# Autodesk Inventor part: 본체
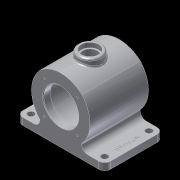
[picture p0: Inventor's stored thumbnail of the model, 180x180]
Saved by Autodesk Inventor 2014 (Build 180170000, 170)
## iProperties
Company: 한국ATC센터
Created: 2014-08
Part Number: 본체
Document SubType Name: Modeling
Designer: KYOUNG IL JANG
Density: 2.71 g/cm^3
Material: 알루미늄-6061
Mass: 1595.13 g
Surface Area: 933.382 cm^2
Volume: 588.61 cm^3
Appearance: 알루미늄 - 평지
Author: KYOUNG IL JANG
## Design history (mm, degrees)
sketch "스케치1"
  geometry: L1 (-50, 0)-(50, 0); L2 (-36.062, 36.062)-(36.062, 36.062); L3 (36.062, 36.062)-(36.062, -36.062); L4 (36.062, -36.062)-(-36.062, -36.062); L5 (-36.062, -36.062)-(-36.062, 36.062); A1 r 53.623 centre (-3.623, 0) between (36.062, -36.062) and (36.062, 36.062); A2 r 53.623 centre (3.623, 0) between (-36.062, 36.062) and (-36.062, -36.062); A3 r 53.623 centre (0, -3.623) between (36.062, 36.062) and (-36.062, 36.062); A4 r 53.623 centre (0, 3.623) between (-36.062, -36.062) and (36.062, -36.062); 4 further points
  constraints: 11 point on circle, 10 end point, 5 coincident, 4 centre point, 4 horizontal alignment, 3 equal radius, 2 horizontal, 2 parallel, 2 perpendicular, 1 midpoint
  dimensions: "d83" = 51 distance of L2.end point (0, 0); "d84" = 100 distance of L1.end L1.start
extrude "돌출1" new body sketch "스케치1" stored distance "d9" = 100; taper "d10" = 0 deg
node "작업 평면1"
sketch "스케치2"
  geometry: L1 (75, 50)-(-75, 50); L2 (-75, 50)-(-75, -50); L3 (-75, -50)-(75, -50); L4 (75, -50)-(75, 50); 4 further points
  constraints: 8 end point, 3 midpoint, 2 parallel, 2 vertical alignment, 1 horizontal, 1 horizontal alignment, 1 perpendicular
  dimensions: "d14" = 150 distance of L2.end L3.end; "d82" = 100 distance of L1.end L2.end
extrude "돌출2" join sketch "스케치2" distance "d15" = 12; taper "d16" = 0 deg
node "작업 평면3"
  node "작업 평면4"
sketch "스케치3"
  geometry: C1 r 20 at (0, 0); 1 further point
  constraints: 2 coincident, 1 centre point
  dimensions: "d19" = 40 diameter of C1
extrude "돌출3" join sketch "스케치3" stored distance "d23" = 12; taper "d24" = 0 deg
node "작업 평면6"
  node "작업 평면5"
sketch "스케치4"
  geometry: C1 r 37.5 at (0, 0); 1 further point
  constraints: 1 centre point, 1 coincident
  dimensions: "d25" = 75 diameter of C1
extrude "돌출4" cut sketch "스케치4" stored distance "d26" = 76; taper "d27" = 0 deg
sketch "스케치5"
  geometry: C1 r 30 at (0, 0); 1 further point
  constraints: 1 centre point, 1 coincident
  dimensions: "d28" = 60 diameter of C1
extrude "돌출5" cut sketch "스케치5" stored distance "d29" = 116; taper "d30" = 0 deg
hole "구멍1" diameter "d33" = 25; stored, may be unused: countersink angle "d37" = 90 deg, drill point angle "d39" = 0 deg; dims "d31" = 10, "d32" = 10, "d34" = 6, "d35" = 30, "d36" = 8, "d38" = 40
sketch "스케치6"
  geometry: L1 (-75, -50)-(-75, 50) reference; L2 (-75, 50)-(75, 50) reference; L3 (75, -50)-(-75, -50) reference; L4 (75, 50)-(75, -50) reference; L5 (0, -50)-(0, 50); L6 (-75, 0)-(75, 0); L7 (-63, -38)-(63, 38); C1 r 5.5 at (-63, -38); C2 r 5.5 at (-63, 38); C3 r 5.5 at (63, -38); C4 r 5.5 at (63, 38); 2 further points
  constraints: 6 end point, 6 midpoint, 4 centre point, 2 equal radius, 2 horizontal alignment, 2 vertical alignment
  dimensions: "d49" = 11 diameter of C1; "d50" = 11 diameter of C2; "d100" = 12 distance from line of L2 C2.centre; "d101" = 12 distance from line of C2.centre L1
extrude "돌출6" cut sketch "스케치6" distance "d53" = 116; taper "d54" = 0 deg
sketch "스케치8"
  geometry: L1 (75, 50)-(75, -50) reference; 2 further points
  constraints: 1 horizontal alignment, 1 other
  dimensions: "d55" = 12 distance from line of L1 point (63, 0)
feature "엠보싱1" sketch "스케치8" dims "d57" = 1, "d58" = 0, "d83" = 51, "d84" = 100
fillet "모깎기2" dims "d60" = 10
fillet "모깎기5" dims "d63" = 10
fillet "모깎기7" dims "d65" = 3
sketch "스케치9"
  geometry: L1 (0, 0)-(-28.284, 28.284); L2 (0, 0)-(0, 40); C1 r 30 at (0, 0) reference; A1 r 40 centre (0, 0) between (-28.284, 28.284) and (0, 40); 1 further point
  constraints: 4 end point, 2 coincident, 2 point on circle, 1 centre point, 1 vertical
  dimensions: "d66" = 80 diameter of A1; "d67" = 45 deg angle of L1 L2
hole "M4" sketch "스케치9" at (-28.284, 28.284) diameter "d68" = 3.242; stored, may be unused: countersink angle "d72" = 90 deg, drill point angle "d74" = 118 deg; dims "d69" = 8, "d70" = 30, "d71" = 8, "d73" = 10
fillet "모깎기8" dims "d78" = 3
chamfer "모따기1" distance "d79" = 1; stored, may be unused: second distance "d80" = 2, angle "d81" = 45 deg
node "솔리드1"
pattern_circular "원형 패턴1" dims angle "d76" = 360 deg
mirror "대칭1"
